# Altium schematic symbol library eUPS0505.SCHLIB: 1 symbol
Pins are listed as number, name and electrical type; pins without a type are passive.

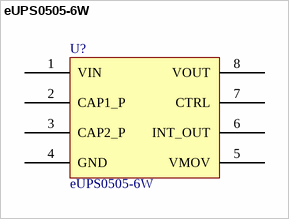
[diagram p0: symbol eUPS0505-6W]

## eUPS0505-6W
designator U?
footprint eUPS0505-6W
pins: 1 VIN, 2 CAP1_P, 3 CAP2_P, 4 GND, 5 VMOV, 6 INT_OUT, 7 CTRL, 8 VOUT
